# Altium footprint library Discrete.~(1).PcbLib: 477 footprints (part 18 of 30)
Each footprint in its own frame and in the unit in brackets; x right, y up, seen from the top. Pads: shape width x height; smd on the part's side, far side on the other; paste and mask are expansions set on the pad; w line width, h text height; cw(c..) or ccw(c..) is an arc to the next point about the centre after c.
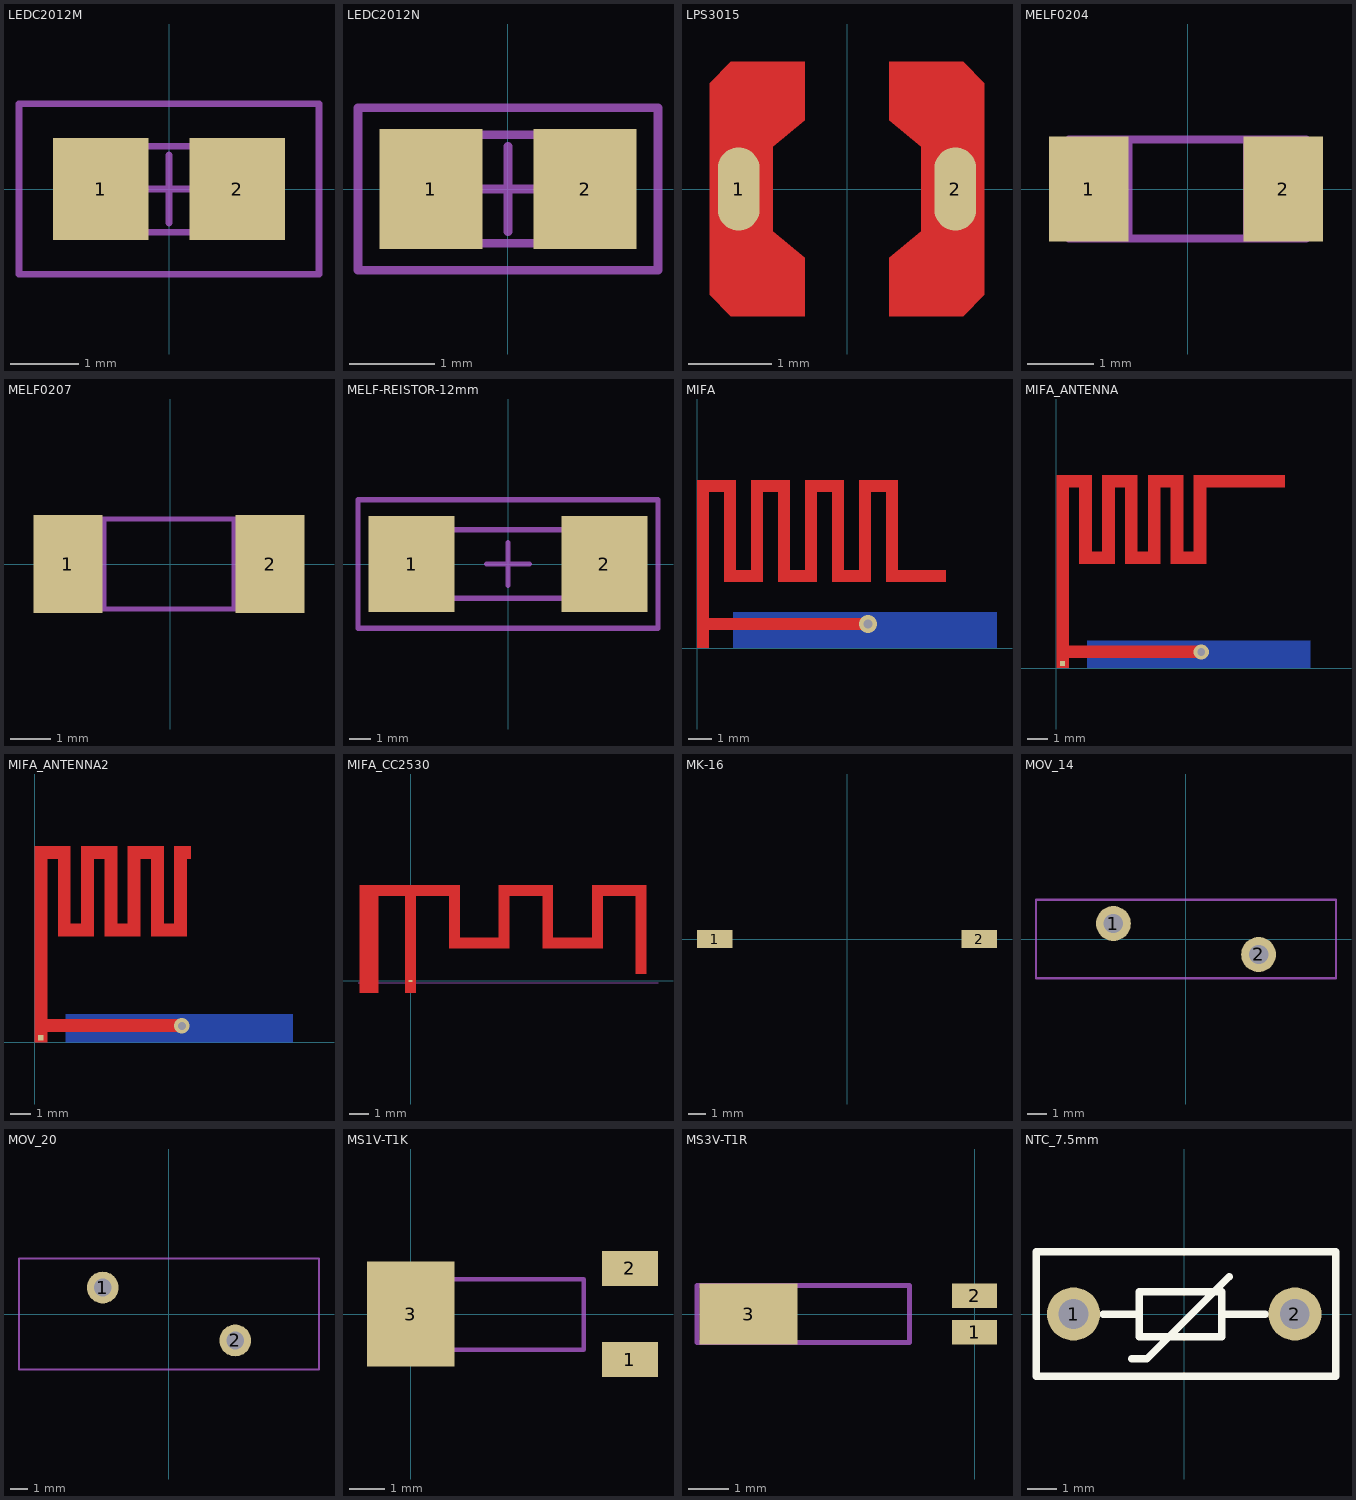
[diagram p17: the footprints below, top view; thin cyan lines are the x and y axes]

## LEDC2012M [mm] "Chip LED, Body 2.0x1.3mm, IPC Low Density"
height 0.65
pads (2):
  rect 1.4x1.5 smd: 1(-1,0) 2(1,0)
Mechanical 13:
  lines w0.1: -1,-0.635 -1,0.626 0.991,0.626 0.991,-0.635 -1,-0.635
Mechanical 15:
  lines w0.1: -0.5,0 0.5,0 ; 0,-0.5 0,0.5 ; -2.2,-1.25 -2.2,1.25 2.2,1.25 2.2,-1.25 -2.2,-1.25
3D body "LED 0805玻璃罩.STEP": height 0.8, standoff 0.31, extent -0.749,-0.626 0.749,0.626
3D body "LED 0805-W.STEP": height 0.67, standoff 0, extent -1,-0.626 1,0.626

## LEDC2012N [mm] "Chip LED, Body 2.0x1.3mm, IPC Medium Density"
height 0.65
pads (2):
  rect 1.2x1.4 smd: 1(-0.9,0) 2(0.9,0)
Mechanical 13:
  lines w0.1: -1.016,-0.635 1,-0.635 1,0.635 -1.016,0.635 -1.016,-0.635
Mechanical 15:
  lines w0.1: -0.5,0 0.5,0 ; 0,-0.5 0,0.5 ; -1.75,-0.95 1.75,-0.95 1.75,0.95 -1.75,0.95 -1.75,-0.95
3D body "LED 0805-W.STEP": height 0.67, standoff 0, extent -1.016,-0.626 0.984,0.626
3D body "LED 0805玻璃罩.STEP": height 0.8, standoff 0.31, extent -0.749,-0.626 0.749,0.626

## LPS3015 [mm]
height 1.4
pads (2):
  oval 0.5x1 smd: 1(-1.3,0) 2(1.3,0)
Top Layer:
  region: -1.395,-1.525 -1.65,-1.27 -1.65,1.27 -1.395,1.525 -0.51,1.525 -0.51,0.825 -0.89,0.51 -0.89,-0.51 -0.51,-0.825 -0.51,-1.525
  region: 1.395,1.525 1.65,1.27 1.65,-1.27 1.395,-1.525 0.51,-1.525 0.51,-0.825 0.89,-0.51 0.89,0.51 0.51,0.825 0.51,1.525
3D body "Coilcraft-LPS3015-DEFAULT.STEP": height 1.5, standoff 0, extent -1.578,-1.578 1.578,1.578

## MELF0204 [mm] "MELF Resistor 3.6mmX1.4mm"
height 1.4
pads (2):
  rect 1.2x1.6 smd: 1(-1.5,0) 2(1.45,0)
Mechanical 13:
  lines w0.127: -0.9,-0.75 -0.9,0.75 ; 0.9,-0.75 0.9,0.75 ; -1.8,-0.75 1.8,-0.75 1.8,0.75 -1.8,0.75 -1.8,-0.75
3D body "56765.stp": height 1.4, standoff 0, extent -1.825,-0.689 1.774,0.711

## MELF0207 [mm] "MELF Resistor 5.8mmX2.2mm"
height 2.2
pads (2):
  rect 1.7x2.4 smd: 1(-2.5,0) 2(2.45,0)
Mechanical 13:
  lines w0.127: -1.625,-1.099 -1.625,1.098 ; 1.575,-1.099 1.575,1.098 ; 2.875,-1.1 -2.9,-1.1 -2.9,1.1 2.9,1.1 2.9,-1.1
3D body: height 2.2, standoff 0, extent -1.625,-1.099 1.575,1.098
3D body: height 2.2, standoff 0, extent -2.925,-1.099 -1.625,1.1
3D body: height 2.2, standoff 0, extent 1.575,-1.1 2.875,1.099

## MELF-REISTOR-12mm [mm]
pads (2):
  rect 4x4.5 smd: 1(-4.5,0) 2(4.5,0)
Mechanical 13:
  lines w0.254: -6.004,1.992 -4.004,1.992 -4,1.988 -4,1.593 4,1.593 3.996,1.597 3.996,1.992 5.996,1.992 5.996,-2 3.996,-2 4,-1.996 4,-1.6 -4,-1.6 -4,-1.996 -4.004,-2 -6.004,-2 -6.004,1.988 -6,1.992
Mechanical 15:
  lines w0.254: -1,0 1,0 ; 0,-1 0,1 ; -7,-3 -7,3 7,3 7,-3 -7,-3
3D body: height 3.98, standoff 0, extent 3.996,-2 5.996,1.992
3D body: height 3.98, standoff 0, extent -6.004,-2 -4.004,1.992
3D body: height 3.59, standoff 0.4, extent -4,-1.6 4,1.593

## MIFA [mm]
via 7.239,1.016 diameter 0.762 hole 0.381
Top Layer:
  rectangle: 0.508,0.762 7.442,1.27
  rectangle: 6.858,2.794 7.366,7.112
  rectangle: 6.223,2.794 6.858,3.302
  rectangle: 5.715,2.794 6.223,7.112
  rectangle: 5.08,6.604 5.715,7.112
  rectangle: 3.937,2.794 4.572,3.302
  rectangle: 4.572,2.794 5.08,7.112
  rectangle: 2.794,6.604 3.429,7.112
  rectangle: 3.429,2.794 3.937,7.112
  rectangle: 2.286,2.794 2.794,7.112
  rectangle: 1.651,2.794 2.286,3.302
  rectangle: 1.143,2.794 1.651,7.112
  rectangle: 0.508,6.604 1.143,7.112
  rectangle: 0,0 0.508,7.112
  rectangle: 7.366,6.604 8.001,7.112
  rectangle: 8.001,2.794 8.509,7.112
  rectangle: 8.509,2.794 10.541,3.302
Bottom Layer:
  rectangle: 1.524,0 12.7,1.524

## MIFA_ANTENNA [mil]
pads (1):
  rect 10x10 smd: 1(12,9)
via 285,32 diameter 30 hole 15
Top Layer:
  rectangle: 290,355 450,380
  rectangle: 0,0 25,380
  rectangle: 20,355 45,380
  rectangle: 45,205 70,380
  rectangle: 65,205 90,230
  rectangle: 90,205 115,380
  rectangle: 135,205 160,380
  rectangle: 110,355 135,380
  rectangle: 180,205 205,380
  rectangle: 155,205 180,230
  rectangle: 200,355 225,380
  rectangle: 225,205 250,380
  rectangle: 245,205 270,230
  rectangle: 270,205 295,380
  rectangle: 20,20 293,45
Bottom Layer:
  rectangle: 60,0 500,55
Top Solder:
  rectangle: -40,0 550,410

## MIFA_ANTENNA2 [mil]
pads (1):
  rect 10x10 smd: 1(12,9)
via 285,32 diameter 30 hole 15
Top Layer:
  rectangle: 20,20 293,45
  rectangle: 270,205 295,380
  rectangle: 245,205 270,230
  rectangle: 225,205 250,380
  rectangle: 200,355 225,380
  rectangle: 155,205 180,230
  rectangle: 180,205 205,380
  rectangle: 110,355 135,380
  rectangle: 135,205 160,380
  rectangle: 90,205 115,380
  rectangle: 65,205 90,230
  rectangle: 45,205 70,380
  rectangle: 20,355 45,380
  rectangle: 0,0 25,380
  rectangle: 290,355 303,380
Bottom Layer:
  rectangle: 60,0 500,55
Top Solder:
  rectangle: -30,0 550,400

## MIFA_CC2530 [mm]
pads (1):
  rect 0.2x0.1 smd: 1(0,0)
Top Layer:
  region: -2.548,-0.608 -2.551,-0.608 -2.555,-0.606 -2.559,-0.602 -2.561,-0.597 -2.561,-0.595 -2.561,4.795 -2.561,4.798 -2.559,4.803 -2.555,4.806 -2.551,4.808 -2.548,4.808 2.452,4.808 2.455,4.808 2.459,4.806 2.463,4.803 2.465,4.798 2.465,4.795 2.465,2.168 4.439,2.168 4.439,4.795 4.439,4.798 4.441,4.803 4.445,4.806 4.449,4.808 4.452,4.808 7.152,4.808 7.155,4.808 7.159,4.806 7.163,4.803 7.165,4.798 7.165,4.795 7.165,2.168 9.139,2.168 9.139,4.795 9.139,4.798 9.141,4.803 9.145,4.806 9.149,4.808 9.152,4.808 11.852,4.808 11.855,4.808 11.859,4.806 11.863,4.803 11.865,4.798 11.865,4.795 11.865,0.355 11.865,0.353 11.863,0.348 11.859,0.344 11.855,0.342 11.852,0.342 11.352,0.342 11.349,0.342 11.345,0.344 11.341,0.348 11.339,0.353 11.339,0.355 11.339,4.282 9.665,4.282 9.665,1.655 9.665,1.653 9.663,1.648 9.659,1.644 9.655,1.642 9.652,1.642 6.652,1.642 6.649,1.642 6.645,1.644 6.641,1.648 6.639,1.653 6.639,1.655 6.639,4.282 4.965,4.282 4.965,1.655 4.965,1.653 4.963,1.648 4.959,1.644 4.955,1.642 4.952,1.642 1.952,1.642 1.949,1.642 1.945,1.644 1.941,1.648 1.939,1.653 1.939,1.655 1.939,4.282 0.265,4.282 0.265,-0.595 0.265,-0.597 0.263,-0.602 0.259,-0.606 0.255,-0.608 0.252,-0.608 -0.248,-0.608 -0.251,-0.608 -0.255,-0.606 -0.259,-0.602 -0.261,-0.597 -0.261,-0.595 -0.261,4.282 -1.635,4.282 -1.635,-0.595 -1.635,-0.597 -1.637,-0.602 -1.641,-0.606 -1.645,-0.608 -1.648,-0.608
Mechanical 13:
  lines w0.025: -2.642,-0.102 12.446,-0.102

## MK-16 [mm]
pads (2):
  rect 2x1 smd: 1(-7.5,0) 2(7.5,0)
3D body "Standex-Meder Electronics-MK16-x-2_WEB.STEP": height 2.41, standoff 0.01, extent -7.8,-1.15 7.8,1.15

## MOV_14 [mm]
pads (2):
  round 1.8 hole 1: 1(-3.75,0.8) 2(3.75,-0.8)
Mechanical 13:
  lines w0.127: -7.75,-2.032 7.75,-2.032 7.75,2.032 -7.75,2.032 -7.75,-2.032
3D body "User Library-S14K25 MOV.STEP": height 18.5, standoff -3, extent -7.75,-2.1 7.75,2.1

## MOV_20 [mm]
pads (2):
  round 1.8 hole 1: 1(-3.75,1.5) 2(3.75,-1.5)
Mechanical 13:
  lines w0.127: -8.496,-3.149 8.496,-3.149 8.496,3.15 -8.496,3.15 -8.496,-3.149
3D body "User Library-MOV 20mm.STEP": height 27.01, standoff -2, extent -11.506,-2.603 11.506,2.604

## MS1V-T1K [mm]
pads (3):
  rect 1.6x1 smd: 1(6.25,-1.3) 2(6.25,1.3)
  rect 2.5x3 smd: 3(0,0)
Mechanical 13:
  lines w0.127: -1.143,-1.016 4.928,-1.016 4.928,0.991 -1.143,0.991 -1.143,-1.016
3D body: height 2, standoff 0, extent -1.145,-1.016 4.955,0.984

## MS3V-T1R [mm]
pads (3):
  rect 1.1x0.6 smd: 1(0,-0.45) 2(0,0.45)
  rect 2.4x1.5 smd: 3(-5.55,0)
Mechanical 13:
  lines w0.127: -6.816,-0.7 -6.816,0.7 -1.6,0.7 -1.6,-0.7 -6.816,-0.7
3D body: height 1.4, standoff 0, extent -6.816,-0.686 -1.616,0.714

## NTC_7.5mm [mm]
pads (2):
  round 1.8 hole 1: 1(-3.75,0) 2(3.75,0)
Top Overlay:
  lines w0.254: -2.75,0 -2.032,0 -1.524,0 ; -1.778,-1.524 -1.27,-1.524 1.524,1.27 ; 1.27,0 2.286,0 2.75,0 ; -5.02,-2.1 5.14,-2.1 5.14,2.1 -5.02,2.1 -5.02,-2.1 ; -1.524,-0.762 1.27,-0.762 1.27,0.762 -1.524,0.762 -1.524,-0.762
3D body "CY 7.5X10X4.STEP": height 10.2, standoff -3.3, extent -4.88,-2 5.12,2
